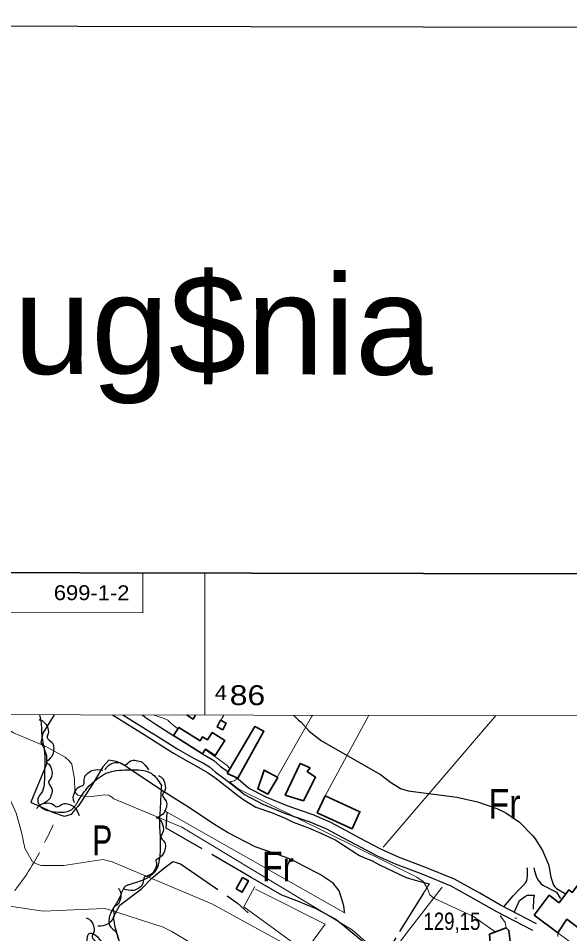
# Model space of a CAD drawing. Extents: x 483847 to 488453, y 4383581 to 4386795.
# Drawn here: x 485906.1 to 486183.5, y 4386334.4 to 4386794.9 of the extents above; entities that cross this region are included whole.
import ezdxf
from ezdxf.enums import TextEntityAlignment as Align

# ---------------------------------------------------------------- set-up
doc = ezdxf.new("R2010")
doc.units = 0
doc.header["$LTSCALE"] = 3.8
doc.linetypes.add('DOTTED', pattern=[1.5, 0.3, -1.2])
doc.linetypes.add('LONG_DASHED', pattern=[7.5, 6, -1.5])
for name, color, linetype, lineweight in [('1', 7, 'Continuous', 13), ('15', 7, 'LONG_DASHED', 13), ('2', 7, 'DOTTED', 13), ('25', 7, 'LONG_DASHED', 25), ('27', 7, 'Continuous', 25), ('36', 7, 'Continuous', 25), ('38', 7, 'Continuous', 25), ('47', 7, 'Continuous', 35), ('51', 7, 'Continuous', 13), ('7', 7, 'Continuous', 13), ('8', 7, 'Continuous', 25), ('9', 7, 'Continuous', 13)]:
    doc.layers.add(name, color=color, linetype=linetype, lineweight=lineweight)
doc.layers.add('31', color=7, linetype='Continuous')

msp = doc.modelspace()

# ---------------------------------------------------------------- linework, layer by layer
at = {"layer": '1'}
for p, q in [((485968.78, 4386515.91), (485968.74, 4386495.91)), ((486000, 4386444.44), (486000, 4386515.85))]:
    msp.add_line(p, q, dxfattribs=at)
at = {"layer": '1', "lineweight": 25}
msp.add_lwpolyline([(483853.06, 4386794.93), (488453.05, 4386786.19), (488446.96, 4383581.19), (483846.97, 4383589.93)], close=True, dxfattribs=at)
at = {"layer": '1', "lineweight": 35}
msp.add_lwpolyline([(484035.03, 4386519.58), (487752.53, 4386512.52), (487747.86, 4384057.52), (484030.36, 4384064.59)], close=True, dxfattribs=at)
at = {"layer": '1'}
msp.add_lwpolyline([(485818.78, 4386516.19), (485818.74, 4386496.19), (485968.74, 4386495.91)], dxfattribs=at)
msp.add_lwpolyline([(484105.5, 4386448.1), (487681.9, 4386441.2), (487678, 4384129), (484100.5, 4384135.8)], close=True, dxfattribs=at)
at = {"layer": '15'}
msp.add_spline([(485669.49, 4386110.7), (485685.13, 4386128.86), (485703.26, 4386142.48), (485721.48, 4386157.08), (485732.87, 4386172.22), (485748.75, 4386190.98), (485763.29, 4386210.88), (485783.67, 4386229.94), (485800.63, 4386245.68), (485821.91, 4386264.74), (485838.88, 4386275.82), (485851.88, 4386292.82), (485869.08, 4386314.93), (485890.07, 4386339.7), (485910.38, 4386364.39), (485923.72, 4386389.19)], degree=3, dxfattribs=at)
at = {"layer": '25'}
for p, q in [((485923.84, 4386443.71), (485924.38, 4386444.59)), ((485953.47, 4386444.53), (485954.9, 4386443.65))]:
    msp.add_line(p, q, dxfattribs=at)
for points in [[(486069.71, 4386345.24), (486070.17, 4386345.67), (486069.91, 4386348.45), (486068.9, 4386351.77), (486067.46, 4386356.06), (486064.59, 4386359.78), (486057.98, 4386364.23), (486049.48, 4386368.55), (486045.76, 4386370.63), (486040.84, 4386372.73), (486025.23, 4386378.2), (486011.38, 4386385.38), (486004.91, 4386389.37), (485990.86, 4386398.66), (485977.77, 4386406.8), (485961.05, 4386418.07), (485958.08, 4386419.99), (485955.39, 4386421.07), (485951.65, 4386421.65), (485948.6, 4386418.32), (485945.98, 4386413.78), (485943.45, 4386409.69), (485937.46, 4386400.25), (485936.01, 4386398.39), (485934.17, 4386396.32), (485932.72, 4386394.31), (485929.41, 4386393.38), (485923.51, 4386395.34), (485918.51, 4386397.67), (485912.85, 4386400.3), (485912.63, 4386400.68), (485920.48, 4386419.85), (485920.46, 4386423.9), (485918.88, 4386428.65), (485917.63, 4386430.54), (485918.68, 4386435.33), (485923.84, 4386443.71)], [(485954.9, 4386443.65), (485969.47, 4386434.6), (485984.19, 4386425.16), (485992.75, 4386420.31), (485996.92, 4386418), (486001.38, 4386415.46), (486005.02, 4386413.08), (486012.37, 4386407.28), (486015.86, 4386404.53), (486019.57, 4386401.77), (486025.67, 4386398.16), (486033.43, 4386395.34), (486040.3, 4386392.54), (486044.47, 4386390.53), (486052.16, 4386387.65), (486058.27, 4386385.01), (486063.04, 4386382.76), (486065.8, 4386381.45), (486067.44, 4386380.52), (486069.74, 4386378.92), (486076.88, 4386374.24), (486077.85, 4386373.7), (486079.56, 4386372.85), (486084.19, 4386371.06), (486088.21, 4386368.82), (486094.47, 4386365.88), (486101.32, 4386362.71), (486105.81, 4386361.29), (486108.35, 4386360.73), (486112.91, 4386359.54)], [(486109.93, 4386354.85), (486096.01, 4386332.39), (486093.79, 4386328.82), (486089.41, 4386327.31), (486086.93, 4386326.97), (486086.41, 4386326.98), (486086.11, 4386327.06), (486084.46, 4386327.68), (486080.88, 4386329.08), (486069.17, 4386338.86), (486065.38, 4386341.84), (486055.93, 4386346.85), (486046.31, 4386351.04), (486038.62, 4386353.77), (486023.21, 4386362.77), (485980.57, 4386387.55), (485981.05, 4386395.47)], [(485956.74, 4386322.37), (485957.02, 4386330.56), (485954.87, 4386337.79), (485954.04, 4386342.83), (485957.28, 4386348.79), (485968.05, 4386357.04), (485973.23, 4386362.44), (485979.91, 4386367.75), (485983.93, 4386370.77), (485987.74, 4386369.59), (486016.42, 4386349.82), (486021.76, 4386344.94)]]:
    msp.add_lwpolyline(points, dxfattribs=at)
at = {"layer": '27'}
for points in [[(485916.75, 4386444.61), (485917.49, 4386441.35), (485918.05, 4386433.39), (485919.09, 4386427.6), (485919.51, 4386420.46), (485919.28, 4386414.31), (485917.72, 4386405.18), (485915.95, 4386402.28), (485916.15, 4386400.18), (485926.36, 4386395.6), (485933.06, 4386396.93), (485936.42, 4386401.39), (485940.64, 4386407.4), (485952.01, 4386415.72), (485962.23, 4386416.85), (485972.94, 4386415.12), (485978.1, 4386409.04)], [(485916.43, 4386442.22), (485918.09, 4386441.61), (485920.59, 4386438.75), (485921.15, 4386435.1), (485920.63, 4386433.12), (485923.11, 4386430.56), (485923.94, 4386427.69), (485923.49, 4386424.7), (485920.34, 4386420.87)], [(485920.1, 4386420.72), (485921.51, 4386419.64), (485923.02, 4386416.16), (485922.44, 4386412.51), (485921.34, 4386410.78), (485922.91, 4386407.59), (485922.83, 4386404.6), (485921.5, 4386401.89), (485917.33, 4386399.2)], [(485949.88, 4386416.82), (485950.78, 4386418.35), (485954.04, 4386420.3), (485957.73, 4386420.2), (485959.59, 4386419.33), (485962.54, 4386421.31), (485965.51, 4386421.62), (485968.37, 4386420.64), (485971.58, 4386416.86)], [(485934.44, 4386400.29), (485933.88, 4386401.98), (485934.56, 4386405.71), (485937.07, 4386408.42), (485938.95, 4386409.25), (485939.41, 4386412.77), (485941.13, 4386415.21), (485943.75, 4386416.72), (485948.71, 4386416.64)], [(485976.65, 4386414.01), (485978.13, 4386413.04), (485979.91, 4386409.68), (485979.61, 4386406), (485978.65, 4386404.19), (485980.46, 4386401.13), (485980.61, 4386398.15), (485979.49, 4386395.34), (485975.54, 4386392.34)], [(485978.1, 4386409.04), (485977.69, 4386401.47), (485977.49, 4386397.57), (485977.14, 4386388.87), (485977.44, 4386383.77), (485977.48, 4386375.66), (485974.93, 4386365.79), (485961.93, 4386359.08), (485960.27, 4386358.42), (485957.35, 4386353.29), (485952.49, 4386344.43), (485951.68, 4386339.86), (485952.03, 4386338.58), (485955.14, 4386335.31), (485956.08, 4386332.9), (485956.87, 4386330.19), (485957.57, 4386326.87), (485957.63, 4386325.6), (485955.45, 4386325.33), (485946.24, 4386332.44), (485941.62, 4386334.31), (485940.77, 4386332.89), (485941.08, 4386328.16), (485941.91, 4386317.79), (485941.97, 4386311.71), (485942.01, 4386304.44), (485941.77, 4386297.84), (485939.11, 4386295.25), (485931.55, 4386296.56), (485930.77, 4386299.64), (485929.9, 4386302.28), (485923.45, 4386302.53), (485916.02, 4386302.48), (485911.9, 4386302.47), (485912.01, 4386300.21), (485911.66, 4386296.39), (485909.25, 4386290.57), (485906.55, 4386285.06), (485904.62, 4386281.79), (485897.13, 4386282.19), (485894.28, 4386282.46), (485893.11, 4386279.4), (485890.79, 4386274.86), (485889.85, 4386271.64), (485890.31, 4386272.46), (485912.07, 4386256.62), (485918.29, 4386251.35), (485926.44, 4386243.73), (485928.55, 4386239.35), (485928.73, 4386235.89), (485927.36, 4386229.24), (485906.94, 4386244.24), (485900.68, 4386242.37), (485894.83, 4386237.43), (485890.72, 4386232.84), (485886.13, 4386232.38), (485861.89, 4386237.53), (485854.96, 4386240.93), (485846.5, 4386246.9), (485842.66, 4386251.76), (485835.03, 4386253.37), (485814.48, 4386243.08), (485810.53, 4386239.69), (485803.75, 4386238.36), (485798.04, 4386237.69), (485791.69, 4386239.81), (485789.69, 4386246.29), (485789.61, 4386246.29), (485788.58, 4386247.58), (485780.18, 4386258.21), (485774.86, 4386258.88), (485762.26, 4386259.22), (485746.2, 4386259.07), (485729.6, 4386258.26), (485716.66, 4386255.59), (485715.98, 4386255), (485703.77, 4386246.32), (485696.87, 4386235.77), (485694.55, 4386231.3), (485682.79, 4386227.41), (485672.44, 4386227.79), (485665.18, 4386229.09), (485656.13, 4386236.05), (485650.69, 4386241.01)], [(485915.4, 4386397.44), (485916.54, 4386398.8), (485920.07, 4386400.17), (485923.69, 4386399.45), (485925.38, 4386398.29), (485928.63, 4386399.74), (485931.61, 4386399.55), (485934.27, 4386398.11), (485936.8, 4386393.84)], [(485975.46, 4386393.06), (485976.98, 4386392.15), (485978.89, 4386388.87), (485978.75, 4386385.18), (485977.86, 4386383.33), (485979.8, 4386380.35), (485980.07, 4386377.38), (485979.06, 4386374.53), (485975.24, 4386371.36)], [(485975.27, 4386371.39), (485975.62, 4386369.65), (485974.49, 4386366.03), (485971.67, 4386363.65), (485969.7, 4386363.06), (485968.81, 4386359.62), (485966.81, 4386357.41), (485964.02, 4386356.23), (485959.11, 4386356.92)], [(485956.46, 4386357.27), (485957.38, 4386355.75), (485957.54, 4386351.96), (485955.69, 4386348.77), (485954.05, 4386347.54), (485954.37, 4386344), (485953.23, 4386341.24), (485951.01, 4386339.19), (485946.15, 4386338.18)], [(485940.22, 4386342.47), (485941.8, 4386341.66), (485943.92, 4386338.52), (485944.02, 4386334.83), (485943.26, 4386332.92), (485945.4, 4386330.08), (485945.87, 4386327.13), (485945.05, 4386324.22), (485941.45, 4386320.81)]]:
    msp.add_spline(points, degree=3, dxfattribs=at)
at = {"layer": '36'}
for p, q in [((485958.73, 4386444.52), (485959.23, 4386444.17)), ((485959.23, 4386444.17), (485960.09, 4386443.64)), ((485968.47, 4386444.51), (485969.59, 4386443.62)), ((485969.59, 4386443.62), (485969.89, 4386443.38))]:
    msp.add_line(p, q, dxfattribs=at)
for points in [[(485960.09, 4386443.64), (485972.91, 4386435.65), (485974.99, 4386434.48)], [(485969.89, 4386443.38), (485974.94, 4386439.93), (485984.36, 4386433.94)], [(485974.99, 4386434.48), (485986.32, 4386427.31), (485994.65, 4386422.54), (485998.97, 4386420.3), (486002.25, 4386418.45), (486005.36, 4386415.71), (486009.59, 4386412.64), (486015.46, 4386408.13), (486019.91, 4386404.47), (486029.22, 4386399.61), (486040.03, 4386395.1), (486051.72, 4386391.11)], [(485998.78, 4386424.94), (486000.81, 4386423.66), (486004.47, 4386421.63), (486007.76, 4386418.78), (486011.73, 4386415.89)], [(486053.43, 4386394.57), (486041.36, 4386398.68), (486030.81, 4386403.08), (486022.01, 4386407.71), (486017.89, 4386411.18), (486016, 4386412.63)], [(486166.79, 4386339.38), (486148.76, 4386348.75), (486138.31, 4386354.74), (486125.51, 4386361.79), (486110.65, 4386367.88), (486097.4, 4386373), (486088.44, 4386376.94), (486077.92, 4386382.5), (486070.93, 4386386.27), (486062.96, 4386390.53), (486054.41, 4386394.18), (486053.43, 4386394.57)], [(486165.01, 4386335.95), (486146.91, 4386345.36), (486136.42, 4386351.37), (486123.84, 4386358.3), (486109.22, 4386364.29), (486095.93, 4386369.43), (486086.76, 4386373.46), (486076.11, 4386379.09), (486069.11, 4386382.87), (486061.29, 4386387.04), (486052.94, 4386390.61), (486051.72, 4386391.11)]]:
    msp.add_lwpolyline(points, dxfattribs=at)
at = {"layer": '38'}
for points in [[(486150.43, 4386347.88), (486155.07, 4386353.53), (486157.81, 4386356.34), (486159.94, 4386358.56), (486161.31, 4386359.97), (486161.93, 4386361.09), (486162.34, 4386363.48), (486162.32, 4386367.08), (486162.1, 4386367.54)], [(486165.4, 4386367.64), (486165.83, 4386365.98), (486166.83, 4386362.82), (486167.64, 4386361.38), (486168.96, 4386359.64), (486170, 4386358.87), (486176.78, 4386355.32), (486178.69, 4386352.37), (486178.76, 4386352.07)], [(486155.65, 4386345.17), (486158.19, 4386351.09), (486161.22, 4386353.29), (486161.97, 4386353.66), (486162.27, 4386353.73), (486163.33, 4386353.79), (486164.3, 4386353.77), (486165.2, 4386353.76), (486165.65, 4386353.76), (486165.65, 4386353.38), (486165.33, 4386352.11), (486165.1, 4386346.71)]]:
    msp.add_lwpolyline(points, dxfattribs=at)
at = {"layer": '47'}
for p, q in [((485990.9, 4386444.46), (485992.28, 4386443.57)), ((485994.78, 4386443.57), (485995.35, 4386444.45))]:
    msp.add_line(p, q, dxfattribs=at)
msp.add_lwpolyline([(485992.28, 4386443.57), (485994.04, 4386442.43), (485994.78, 4386443.57)], dxfattribs=at)
for points in [[(486007.84, 4386441.78), (486006.17, 4386438.43), (486008.97, 4386437.04), (486010.64, 4386440.39)], [(485984.24, 4386434.17), (485998.74, 4386424.88), (486000.25, 4386427.24), (486005.23, 4386424.05), (486010.03, 4386431.55), (486003.62, 4386435.64), (486001.24, 4386431.91), (485998.8, 4386433.45), (485997.55, 4386431.47), (485986.89, 4386438.17)], [(486011.2, 4386414.95), (486025.05, 4386438.61), (486029.67, 4386436.29), (486016.57, 4386412.69)], [(486036.76, 4386412.93), (486031.69, 4386404.67), (486026.63, 4386407.3), (486029.76, 4386416.71)], [(486040.31, 4386404.1), (486047.89, 4386420.05), (486052.89, 4386417.8), (486051.44, 4386416.1), (486055.67, 4386413.11), (486049.58, 4386401.34)], [(486056.54, 4386395.24), (486074.12, 4386387.23), (486078.01, 4386395.76), (486060.43, 4386403.77)], [(486018.93, 4386362.69), (486015.77, 4386357.05), (486018.83, 4386355.33), (486021.99, 4386360.97)], [(486177.46, 4386334.9), (486165.66, 4386343.78), (486173.16, 4386353.75), (486178.14, 4386349.99), (486183.04, 4386356.48), (486184.75, 4386355.18), (486188.44, 4386360.04), (486200.81, 4386350.64), (486189.64, 4386335.95), (486182.1, 4386341.66)], [(486154.63, 4386322.62), (486152.94, 4386336.08), (486151.54, 4386337.3), (486143.16, 4386334.27), (486144.18, 4386321.35)]]:
    msp.add_lwpolyline(points, close=True, dxfattribs=at)
at = {"layer": '51'}
for p, q in [((486008.95, 4386443.54), (486007.37, 4386440.83)), ((486009.47, 4386444.43), (486008.95, 4386443.54)), ((486036.4, 4386413.13), (486053.56, 4386443.46)), ((486053.56, 4386443.46), (486054.06, 4386444.34)), ((486060.54, 4386403.72), (486081.98, 4386443.4)), ((486081.98, 4386443.4), (486082.46, 4386444.29)), ((486145.68, 4386443.28), (486146.44, 4386444.16)), ((486089.69, 4386377.95), (486145.68, 4386443.28)), ((485979.5, 4386396.34), (486070.53, 4386344.76)), ((486112.91, 4386359.54), (486109.46, 4386354.11))]:
    msp.add_line(p, q, dxfattribs=at)
for points in [[(486025.53, 4386356.89), (486060.47, 4386339.21), (486050.46, 4386325.45), (486033.14, 4386306.51), (486005.96, 4386279.58), (485988.9, 4386256.72), (485969.63, 4386236.58), (485941.16, 4386202.63), (485920.25, 4386178.54), (485936.45, 4386162.1)], [(486025.17, 4386358.24), (486019.55, 4386347.97), (486050.52, 4386325.39)], [(486119.34, 4386357.8), (486102.59, 4386336.13), (486084.7, 4386312.45), (486083.02, 4386310.67)], [(486151.54, 4386337.3), (486150.97, 4386340.01), (486148.62, 4386343.19), (486149.15, 4386344.2)], [(486222.96, 4386300.79), (486211.55, 4386310.03), (486201.16, 4386317.98), (486192.17, 4386324.41), (486186.6, 4386328.17), (486177.46, 4386334.9), (486177.52, 4386332.97)]]:
    msp.add_lwpolyline(points, dxfattribs=at)
at = {"layer": '7'}
msp.add_line((486155.94, 4386342.32), (486156.94, 4386342.32), dxfattribs=at)
at = {"layer": '8'}
msp.add_lwpolyline([(486044.58, 4386444.36), (486047.02, 4386441.89), (486048.18, 4386441.01), (486052.52, 4386436.36), (486058.66, 4386431.38), (486088.3, 4386414.46), (486093.3, 4386410.58), (486098.45, 4386407.44), (486102.29, 4386406.25), (486126.68, 4386403.09), (486137.16, 4386400.68), (486146.87, 4386397.38), (486151.45, 4386395.17), (486158.29, 4386390.47), (486164.93, 4386383.66), (486166.13, 4386382.11), (486169.74, 4386376.36), (486172.77, 4386369.23), (486173.21, 4386367.8), (486174.09, 4386362.94), (486175.36, 4386358.9), (486176.03, 4386357.98), (486176.84, 4386357.15), (486180.92, 4386354.88), (486181.6, 4386354.58)], dxfattribs=at)
at = {"layer": '9'}
for points in [[(486000.47, 4386325.31), (485983.36, 4386335.61), (485978.97, 4386337.66), (485951.09, 4386346.8), (485949.3, 4386347.13), (485918.64, 4386345.76), (485902.9, 4386348.08), (485899.71, 4386349.78), (485897.02, 4386351.94), (485891.5, 4386363.56), (485887.9, 4386380.99), (485885.45, 4386386.64), (485879.47, 4386396.55), (485875.36, 4386401.85), (485861.37, 4386414.11), (485848.45, 4386422.46), (485840.51, 4386426.11), (485807.47, 4386436.12), (485788.67, 4386444.85)], [(486047.64, 4386325.34), (486003.46, 4386349.39), (485953.34, 4386370.61), (485948.58, 4386371.79), (485929.09, 4386368.66), (485917.57, 4386368.74), (485915.24, 4386369.52), (485913.29, 4386370.63), (485909.38, 4386377.38), (485907.81, 4386385.49), (485905, 4386395.02), (485901.11, 4386404.04), (485896.79, 4386408.59), (485854.09, 4386444.16), (485853.52, 4386444.52), (485853.38, 4386444.64), (485853.24, 4386444.73)], [(485891.73, 4386444.65), (485891.89, 4386444.51), (485892.55, 4386443.6), (485897.9, 4386439.09), (485903.65, 4386435.46), (485919.61, 4386428.73), (485929.79, 4386423.31), (485931.61, 4386421.58), (485932.99, 4386419.75), (485934.33, 4386412.31), (485934.52, 4386406.01), (485935.17, 4386404.9), (485936.09, 4386404.06), (485941.54, 4386403.34), (485949.65, 4386404.29), (485951.71, 4386404.13), (485953.13, 4386403.19), (485954.19, 4386402.34), (485988.32, 4386388.08), (486074.04, 4386336.31), (486089.99, 4386322.37), (486091.9, 4386320.2), (486129.04, 4386301.02)], [(485986.42, 4386437.45), (485982.92, 4386440.26), (485981.39, 4386441.77), (485979.58, 4386442.76), (485974.06, 4386444.49)], [(486012.64, 4386417.41), (486012.23, 4386417.93), (486011.14, 4386419.06), (486000.16, 4386427.1)], [(486146.08, 4386335.33), (486135.18, 4386343.11), (486115.16, 4386352.34), (486114.08, 4386353.16), (486113.22, 4386353.99), (486111.93, 4386357.12), (486109.74, 4386360.64), (486106.53, 4386362.85), (486016.75, 4386407.26), (486013.48, 4386409.86), (486012.78, 4386410.59), (486013, 4386410.91), (486013.19, 4386410.99), (486013.43, 4386411.07), (486014.79, 4386411.29), (486015.76, 4386412.03), (486015.76, 4386412.43), (486015.65, 4386412.91), (486015.53, 4386413.13)]]:
    msp.add_lwpolyline(points, dxfattribs=at)

# ---------------------------------------------------------------- texts
at = {"layer": '2', "width": 1.05}
msp.add_text('Santa Eug$nia ', height=50, rotation=359.889, dxfattribs=at).set_placement((485894, 4386616.05), align=Align.CENTER)
at = {"layer": '2'}
for s, height, rotation, width, p in [('699-1-2', 7.5, 359.891, 1.1, (485924, 4386502.24)), ('4', 7.5, 359.889, 1.1, (486004.99, 4386451.93)), ('86  ', 10, 359.889, 1.2, (486012.48, 4386449.42))]:
    msp.add_text(s, height=height, rotation=rotation, dxfattribs=dict(at, width=width)).set_placement(p)
at = {"layer": '31'}
for s, width, p in [('Fr', 0.85, (486150.71, 4386392.23)), ('P', 0.75, (485948.39, 4386373.87)), ('Fr', 0.85, (486036.73, 4386360.71))]:
    msp.add_text(s, height=15, dxfattribs=dict(at, width=width)).set_placement(p, align=Align.CENTER)
at = {"layer": '7', "width": 0.8}
msp.add_text('129,15', height=8.75, dxfattribs=at).set_placement((486109.94, 4386336.32))

doc.saveas('drawing.dxf')
